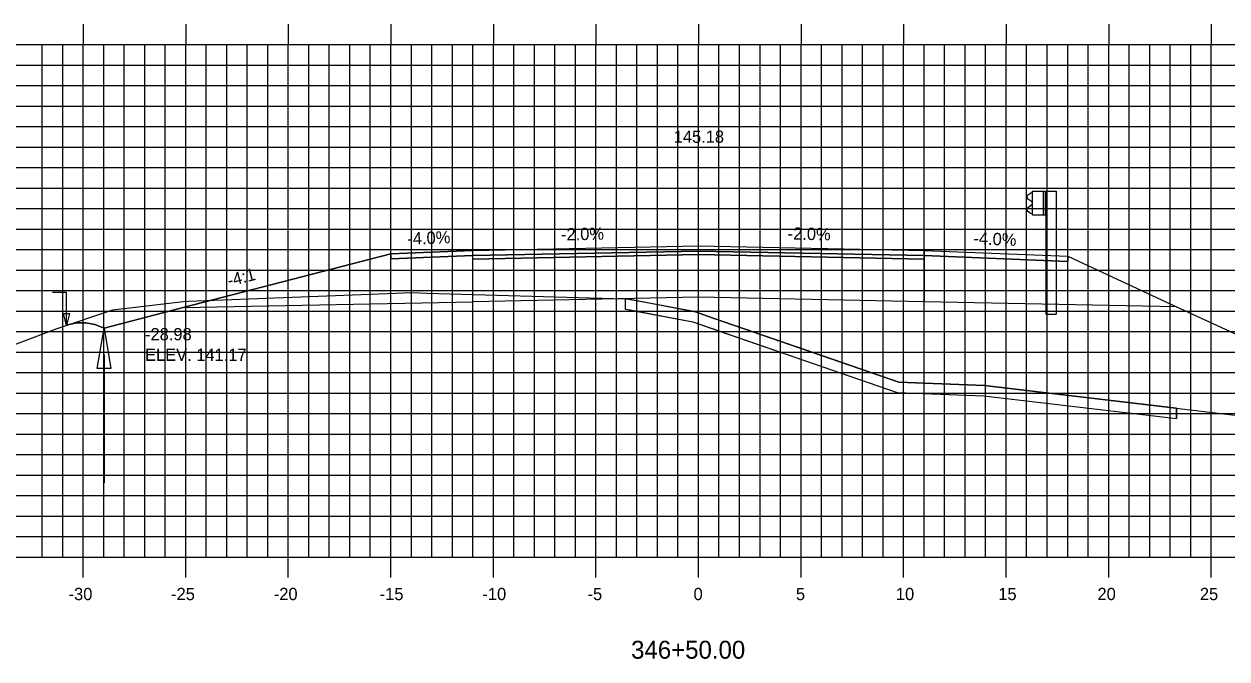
# Model space of a CAD drawing. Extents: x 1143863 to 1144033, y 608981 to 609091.
# Drawn here: x 1143913.7 to 1143972.4, y 609015.4 to 609046.3 of the extents above; entities that cross this region are included whole.
import ezdxf

# ---------------------------------------------------------------- set-up
doc = ezdxf.new("R2010")
doc.units = 0
for name, color, linetype in [('ANNOTATION', 7, 'Continuous'), ('D_Drainage_Ditch_Line', 7, 'Continuous'), ('D_Guardrail_Beam_Rt', 7, 'Continuous'), ('D_Guardrail_ConcBarrier', 7, 'Continuous'), ('D_Roadway_Centerline', 7, 'Continuous'), ('D_Roadway_Centerline_Text', 7, 'Continuous'), ('D_Roadway_Edge_Shoulder', 7, 'Continuous'), ('D_Roadway_Edge_TW', 7, 'Continuous'), ('D_Roadway_Pavement', 7, 'Continuous'), ('D_Roadway_SlopeLines', 7, 'Continuous'), ('D_Roadway_SubGrade', 7, 'Continuous'), ('D_Text_Standard', 7, 'Continuous'), ('H_V ANNOTATION', 7, 'Continuous'), ('MAJOR', 7, 'Continuous'), ('MINOR', 7, 'Continuous'), ('S_Roadway_Centerline', 7, 'Continuous'), ('SHADING', 7, 'Continuous')]:
    doc.layers.add(name, color=color, linetype=linetype)

msp = doc.modelspace()

# ---------------------------------------------------------------- linework, layer by layer
msp.add_lwpolyline([(1143915.832, 609031.661), (1143916.276, 609031.761), (1143916.721, 609031.769), (1143917.165, 609031.685), (1143917.609, 609031.509), (1143921.469, 609032.509), (1143931.592, 609035.131), (1143931.593, 609035.131), (1143935.593, 609035.291), (1143946.593, 609035.511), (1143957.593, 609035.291), (1143964.593, 609035.011), (1143969.901, 609032.545), (1143972.053, 609031.545), (1143981.155, 609027.316)])
at = {"layer": 'D_Drainage_Ditch_Line'}
msp.add_line((1143917.609, 609030.196), (1143917.608, 609023.953), dxfattribs=at)
msp.add_lwpolyline([(1143917.937, 609029.54), (1143917.281, 609029.54), (1143917.609, 609031.509)], close=True, dxfattribs=at)
at = {"layer": 'D_Guardrail_Beam_Rt'}
for p, q in [((1143962.781, 609038.075), (1143962.637, 609037.975)), ((1143962.871, 609038.096), (1143962.797, 609038.082)), ((1143962.637, 609037.832), (1143962.833, 609037.696)), ((1143962.833, 609037.497), (1143962.637, 609037.361)), ((1143962.866, 609037.632), (1143962.866, 609037.561)), ((1143962.637, 609037.218), (1143962.781, 609037.118)), ((1143962.797, 609037.111), (1143962.871, 609037.096))]:
    msp.add_line(p, q, dxfattribs=at)
for centre, major_axis, start_param, end_param in [((1143962.805, 609038.041), (-0.0417, 0), 4.907132, 5.323254), ((1143962.688, 609037.904), (-0.0877, 0), 5.323254, 7.243116), ((1143962.787, 609037.632), (0.0789, 0), 0, 0.959931), ((1143962.787, 609037.561), (0.0789, 0), 5.323254, 6.283185), ((1143962.688, 609037.289), (-0.0877, 0), 5.323254, 7.243116), ((1143962.805, 609037.152), (-0.0417, 0), 0.959931, 1.376053)]:
    msp.add_ellipse(centre, major_axis=major_axis, ratio=0.995501, start_param=start_param, end_param=end_param, dxfattribs=at)
at = {"layer": 'D_Guardrail_ConcBarrier'}
for p, q in [((1143962.871, 609038.18), (1143963.558, 609038.18)), ((1143962.871, 609037.013), (1143962.871, 609038.18)), ((1143963.392, 609038.18), (1143963.392, 609037.013)), ((1143963.496, 609038.18), (1143963.496, 609037.013)), ((1143963.558, 609038.18), (1143964.029, 609038.18)), ((1143963.558, 609038.18), (1143963.558, 609037.013)), ((1143964.029, 609038.18), (1143964.029, 609032.18)), ((1143963.558, 609037.013), (1143962.871, 609037.013)), ((1143963.537, 609032.18), (1143963.537, 609037.013)), ((1143963.537, 609032.18), (1143964.029, 609032.18))]:
    msp.add_line(p, q, dxfattribs=at)
at = {"layer": 'D_Roadway_Edge_Shoulder'}
for points in [[(1143935.593, 609035.291), (1143931.593, 609035.131), (1143931.593, 609034.881), (1143935.593, 609035.041)], [(1143957.593, 609035.291), (1143964.593, 609035.011), (1143964.593, 609034.761), (1143957.593, 609035.041)]]:
    msp.add_lwpolyline(points, close=True, dxfattribs=at)
at = {"layer": 'D_Roadway_Edge_TW'}
msp.add_lwpolyline([(1143935.593, 609035.041), (1143935.593, 609035.291), (1143946.593, 609035.511), (1143957.593, 609035.291), (1143957.593, 609035.041), (1143946.593, 609035.261)], close=True, dxfattribs=at)
at = {"layer": 'D_Roadway_Pavement'}
msp.add_lwpolyline([(1143935.593, 609034.874), (1143935.593, 609035.041), (1143946.593, 609035.261), (1143957.593, 609035.041), (1143957.593, 609034.874), (1143946.593, 609035.094)], close=True, dxfattribs=at)
at = {"layer": 'D_Roadway_SlopeLines'}
for p, q in [((1143943.019, 609032.935), (1143943.019, 609032.435)), ((1143969.901, 609027.595), (1143969.901, 609027.091))]:
    msp.add_line(p, q, dxfattribs=at)
for points in [[(1143921.469, 609032.509), (1143917.609, 609031.509)], [(1143943.019, 609032.431), (1143943.258, 609032.402), (1143946.319, 609031.81), (1143947.147, 609031.511), (1143956.273, 609028.37), (1143960.502, 609028.208), (1143969.901, 609027.091)], [(1143969.901, 609032.545), (1143972.053, 609031.545)], [(1143917.609, 609031.509), (1143917.165, 609031.685), (1143916.721, 609031.769), (1143916.276, 609031.761), (1143915.832, 609031.661)], [(1143972.053, 609031.545), (1143981.155, 609027.316)]]:
    msp.add_lwpolyline(points, dxfattribs=at)
at = {"layer": 'D_Roadway_SubGrade'}
for points in [[(1143935.593, 609034.874), (1143935.593, 609035.041), (1143931.593, 609034.881), (1143931.593, 609035.131), (1143931.592, 609035.131), (1143921.469, 609032.509), (1143935.593, 609032.791)], [(1143935.593, 609032.791), (1143935.593, 609034.874), (1143946.593, 609035.094), (1143957.593, 609034.874), (1143957.593, 609032.791), (1143946.593, 609033.011)], [(1143957.593, 609034.874), (1143957.593, 609035.041), (1143964.593, 609034.761), (1143964.593, 609035.011), (1143964.593, 609035.011), (1143969.901, 609032.545), (1143957.593, 609032.791)]]:
    msp.add_lwpolyline(points, close=True, dxfattribs=at)
at = {"layer": 'D_Text_Standard'}
msp.add_lwpolyline([(1143915.775, 609031.633), (1143915.781, 609033.238), (1143915.101, 609033.238)], dxfattribs=at)
msp.add_lwpolyline([(1143915.775, 609031.633), (1143915.631, 609032.215), (1143915.922, 609032.214)], close=True, dxfattribs=at)
at = {"layer": 'MAJOR'}
for p, q in [((1143916.593, 609046.337), (1143916.593, 609045.335)), ((1143921.593, 609046.337), (1143921.593, 609045.335)), ((1143926.593, 609046.337), (1143926.593, 609045.335)), ((1143931.593, 609046.337), (1143931.593, 609045.335)), ((1143936.593, 609046.337), (1143936.593, 609045.335)), ((1143941.593, 609046.337), (1143941.593, 609045.335)), ((1143946.593, 609046.337), (1143946.593, 609045.335)), ((1143951.593, 609046.337), (1143951.593, 609045.335)), ((1143956.593, 609046.337), (1143956.593, 609045.335)), ((1143961.593, 609046.337), (1143961.593, 609045.335)), ((1143966.593, 609046.337), (1143966.593, 609045.335)), ((1143971.593, 609046.337), (1143971.593, 609045.335)), ((1143876.593, 609045.335), (1144016.593, 609045.335)), ((1143876.593, 609045.335), (1144016.593, 609045.335)), ((1143916.593, 609020.335), (1143916.593, 609045.335)), ((1143921.593, 609020.335), (1143921.593, 609045.335)), ((1143926.593, 609020.335), (1143926.593, 609045.335)), ((1143931.593, 609020.335), (1143931.593, 609045.335)), ((1143936.593, 609020.335), (1143936.593, 609045.335)), ((1143941.593, 609020.335), (1143941.593, 609045.335)), ((1143946.593, 609020.335), (1143946.593, 609045.335)), ((1143951.593, 609020.335), (1143951.593, 609045.335)), ((1143956.593, 609020.335), (1143956.593, 609045.335)), ((1143961.593, 609020.335), (1143961.593, 609045.335)), ((1143966.593, 609020.335), (1143966.593, 609045.335)), ((1143971.593, 609020.335), (1143971.593, 609045.335)), ((1143876.593, 609040.335), (1144016.593, 609040.335)), ((1143876.593, 609035.335), (1144016.593, 609035.335)), ((1143876.593, 609030.335), (1144016.593, 609030.335)), ((1143876.593, 609025.335), (1144016.593, 609025.335)), ((1143876.593, 609020.335), (1144016.593, 609020.335)), ((1143876.593, 609020.335), (1144016.593, 609020.335)), ((1143916.593, 609019.333), (1143916.593, 609020.335)), ((1143921.593, 609019.333), (1143921.593, 609020.335)), ((1143926.593, 609019.333), (1143926.593, 609020.335)), ((1143931.593, 609019.333), (1143931.593, 609020.335)), ((1143936.593, 609019.333), (1143936.593, 609020.335)), ((1143941.593, 609019.333), (1143941.593, 609020.335)), ((1143946.593, 609019.333), (1143946.593, 609020.335)), ((1143951.593, 609019.333), (1143951.593, 609020.335)), ((1143956.593, 609019.333), (1143956.593, 609020.335)), ((1143961.593, 609019.333), (1143961.593, 609020.335)), ((1143966.593, 609019.333), (1143966.593, 609020.335)), ((1143971.593, 609019.333), (1143971.593, 609020.335))]:
    msp.add_line(p, q, dxfattribs=at)
at = {"layer": 'MINOR'}
for p, q in [((1143914.593, 609020.335), (1143914.593, 609045.335)), ((1143915.593, 609020.335), (1143915.593, 609045.335)), ((1143917.593, 609020.335), (1143917.593, 609045.335)), ((1143918.593, 609020.335), (1143918.593, 609045.335)), ((1143919.593, 609020.335), (1143919.593, 609045.335)), ((1143920.593, 609020.335), (1143920.593, 609045.335)), ((1143922.593, 609020.335), (1143922.593, 609045.335)), ((1143923.593, 609020.335), (1143923.593, 609045.335)), ((1143924.593, 609020.335), (1143924.593, 609045.335)), ((1143925.593, 609020.335), (1143925.593, 609045.335)), ((1143927.593, 609020.335), (1143927.593, 609045.335)), ((1143928.593, 609020.335), (1143928.593, 609045.335)), ((1143929.593, 609020.335), (1143929.593, 609045.335)), ((1143930.593, 609020.335), (1143930.593, 609045.335)), ((1143932.593, 609020.335), (1143932.593, 609045.335)), ((1143933.593, 609020.335), (1143933.593, 609045.335)), ((1143934.593, 609020.335), (1143934.593, 609045.335)), ((1143935.593, 609020.335), (1143935.593, 609045.335)), ((1143937.593, 609020.335), (1143937.593, 609045.335)), ((1143938.593, 609020.335), (1143938.593, 609045.335)), ((1143939.593, 609020.335), (1143939.593, 609045.335)), ((1143940.593, 609020.335), (1143940.593, 609045.335)), ((1143942.593, 609020.335), (1143942.593, 609045.335)), ((1143943.593, 609020.335), (1143943.593, 609045.335)), ((1143944.593, 609020.335), (1143944.593, 609045.335)), ((1143945.593, 609020.335), (1143945.593, 609045.335)), ((1143947.593, 609020.335), (1143947.593, 609045.335)), ((1143948.593, 609020.335), (1143948.593, 609045.335)), ((1143949.593, 609020.335), (1143949.593, 609045.335)), ((1143950.593, 609020.335), (1143950.593, 609045.335)), ((1143952.593, 609020.335), (1143952.593, 609045.335)), ((1143953.593, 609020.335), (1143953.593, 609045.335)), ((1143954.593, 609020.335), (1143954.593, 609045.335)), ((1143955.593, 609020.335), (1143955.593, 609045.335)), ((1143957.593, 609020.335), (1143957.593, 609045.335)), ((1143958.593, 609020.335), (1143958.593, 609045.335)), ((1143959.593, 609020.335), (1143959.593, 609045.335)), ((1143960.593, 609020.335), (1143960.593, 609045.335)), ((1143962.593, 609020.335), (1143962.593, 609045.335)), ((1143963.593, 609020.335), (1143963.593, 609045.335)), ((1143964.593, 609020.335), (1143964.593, 609045.335)), ((1143965.593, 609020.335), (1143965.593, 609045.335)), ((1143967.593, 609020.335), (1143967.593, 609045.335)), ((1143968.593, 609020.335), (1143968.593, 609045.335)), ((1143969.593, 609020.335), (1143969.593, 609045.335)), ((1143970.593, 609020.335), (1143970.593, 609045.335)), ((1143876.593, 609044.335), (1144016.593, 609044.335)), ((1143876.593, 609043.335), (1144016.593, 609043.335)), ((1143876.593, 609042.335), (1144016.593, 609042.335)), ((1143876.593, 609041.335), (1144016.593, 609041.335)), ((1143876.593, 609039.335), (1144016.593, 609039.335)), ((1143876.593, 609038.335), (1144016.593, 609038.335)), ((1143876.593, 609037.335), (1144016.593, 609037.335)), ((1143876.593, 609036.335), (1144016.593, 609036.335)), ((1143876.593, 609034.335), (1144016.593, 609034.335)), ((1143876.593, 609033.335), (1144016.593, 609033.335)), ((1143876.593, 609032.335), (1144016.593, 609032.335)), ((1143876.593, 609031.335), (1144016.593, 609031.335)), ((1143876.593, 609029.335), (1144016.593, 609029.335)), ((1143876.593, 609028.335), (1144016.593, 609028.335)), ((1143876.593, 609027.335), (1144016.593, 609027.335)), ((1143876.593, 609026.335), (1144016.593, 609026.335)), ((1143876.593, 609024.335), (1144016.593, 609024.335)), ((1143876.593, 609023.335), (1144016.593, 609023.335)), ((1143876.593, 609022.335), (1144016.593, 609022.335)), ((1143876.593, 609021.335), (1144016.593, 609021.335))]:
    msp.add_line(p, q, dxfattribs=at)
at = {"layer": 'S_Roadway_Centerline'}
msp.add_lwpolyline([(1143876.593, 609028.445), (1143880.764, 609028.537), (1143893.48, 609029.427), (1143907.327, 609030.275), (1143911.989, 609030.655), (1143912.996, 609030.602), (1143915.271, 609031.477), (1143918.046, 609032.388), (1143921.473, 609032.795), (1143921.72, 609032.822), (1143931.839, 609033.205), (1143932.613, 609033.238), (1143933.341, 609033.203), (1143943.019, 609032.935), (1143943.336, 609032.897), (1143946.452, 609032.294), (1143947.313, 609031.983), (1143956.366, 609028.867), (1143960.542, 609028.707), (1143973.447, 609027.173), (1143980.648, 609027.329), (1143988.842, 609027.119), (1144003.679, 609028.03), (1144016.593, 609029.026)], dxfattribs=at)
at = {"layer": 'SHADING'}
msp.add_lwpolyline([(1143943.019, 609032.935), (1143943.019, 609032.431), (1143946.319, 609031.81), (1143951.71, 609029.941), (1143956.273, 609028.37), (1143960.502, 609028.208), (1143965.202, 609027.65), (1143969.901, 609027.091), (1143969.901, 609027.593), (1143966.994, 609027.94), (1143960.542, 609028.707), (1143958.454, 609028.787), (1143956.366, 609028.867), (1143951.839, 609030.425), (1143947.313, 609031.983), (1143946.452, 609032.294), (1143944.894, 609032.595)], close=True, dxfattribs=at)

# ---------------------------------------------------------------- texts
at = {"layer": 'ANNOTATION'}
for s, rotation, p in [('-2.0%', 1.14576, (1143939.896, 609035.777)), ('-2.0%', 358.85424, (1143950.936, 609035.824)), ('-4.0%', 2.29061, (1143932.409, 609035.565)), ('-4.0%', 357.70939, (1143959.989, 609035.596)), ('-4:1', 14.52411, (1143923.706, 609033.521))]:
    msp.add_text(s, height=0.6, rotation=rotation, dxfattribs=at).set_placement(p)
at = {"layer": 'D_Roadway_Centerline'}
for s, p in [('C', (1143946.587, 609035.511)), ('L', (1143946.593, 609035.504))]:
    msp.add_text(s, height=0.0146, dxfattribs=at).set_placement(p)
at = {"layer": 'D_Roadway_Centerline_Text'}
msp.add_text('145.18', height=0.6, dxfattribs=at).set_placement((1143945.386, 609040.543))
at = {"layer": 'D_Text_Standard'}
for s, p in [('-28.98', (1143919.609, 609030.909)), ('ELEV. 141.17', (1143919.609, 609029.907))]:
    msp.add_text(s, height=0.6, dxfattribs=at).set_placement(p)
at = {"layer": 'H_V ANNOTATION'}
for s, height, p in [('-30', 0.6, (1143915.881, 609018.235)), ('-25', 0.6, (1143920.878, 609018.235)), ('-20', 0.6, (1143925.886, 609018.235)), ('-15', 0.6, (1143931.05, 609018.235)), ('-10', 0.6, (1143936.058, 609018.235)), ('-5', 0.6, (1143941.183, 609018.235)), ('0', 0.6, (1143946.352, 609018.235)), ('5', 0.6, (1143951.344, 609018.235)), ('10', 0.6, (1143956.218, 609018.235)), ('15', 0.6, (1143961.21, 609018.235)), ('20', 0.6, (1143966.047, 609018.235)), ('25', 0.6, (1143971.039, 609018.235)), ('346+50.00', 0.875, (1143943.308, 609015.378))]:
    msp.add_text(s, height=height, dxfattribs=at).set_placement(p)
at = {"layer": 'S_Roadway_Centerline'}
for s, p in [('L', (1143932.604, 609033.23)), ('C', (1143932.607, 609033.238))]:
    msp.add_text(s, height=0.0146, dxfattribs=at).set_placement(p)

doc.saveas('drawing.dxf')
